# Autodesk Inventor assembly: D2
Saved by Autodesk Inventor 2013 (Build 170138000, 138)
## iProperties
Created: 2021-02
Part Number: D2
Document SubType Name: Assembly
Designer: Fede
Author: Fede
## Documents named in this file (2)
- C:\0000 FEDE\16GB\0000 INTERIOR\DE_TMP_BAS\BAS_DTON - demora conexion al energizar\pcb\BOR\turn on\Imported Components\BAS_DTON\D2.iam
- C:\0000 FEDE\16GB\0000 INTERIOR\DE_TMP_BAS\BAS_DTON - demora conexion al energizar\pcb\BOR\turn on\Imported Components\BAS_DTON\sod123.iam
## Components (1 placed, 1 different names)
1. sod123:1 [sub-assembly]
